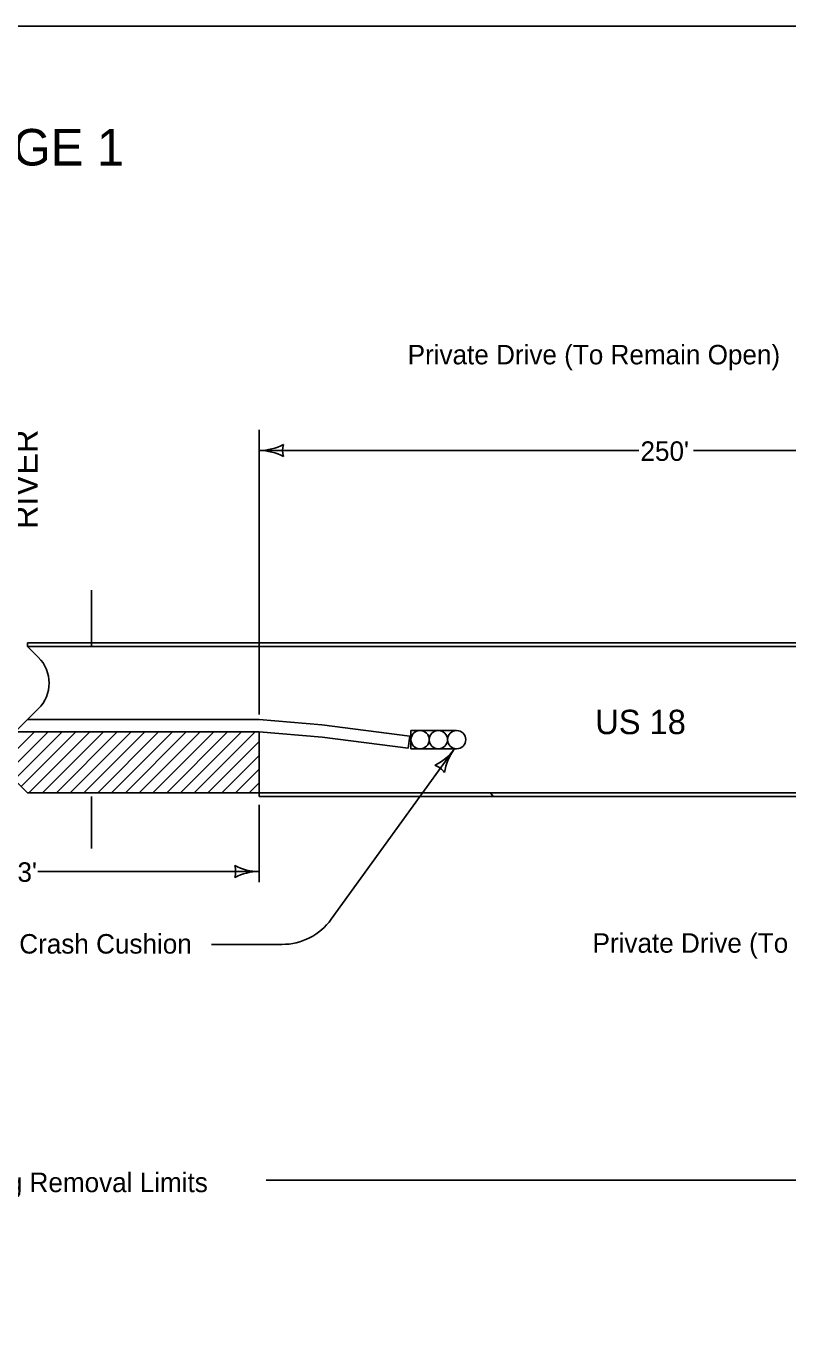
# Model space of a CAD drawing. Extents: x -2134934 to -2122394, y -2140205 to -2137036.
# Drawn here: x -2128661 to -2128036, y -2138106 to -2137036 of the extents above; entities that cross this region are included whole.
import ezdxf

# ---------------------------------------------------------------- set-up
doc = ezdxf.new("R2010")
doc.units = 0
for name, color, linetype in [('Barrier', 7, 'Continuous'), ('BridgeSuperStructureExisting', 7, 'Continuous'), ('Default', 7, 'Continuous'), ('dsnCellsNorthArrow', 7, 'Continuous'), ('DsnShtPlotIdentification', 7, 'Continuous'), ('DsnShtPlotShape', 7, 'Continuous')]:
    doc.layers.add(name, color=color, linetype=linetype)

msp = doc.modelspace()

# ---------------------------------------------------------------- linework, layer by layer
at = {"layer": 'BridgeSuperStructureExisting'}
for p, q in [((-2128470.1, -2137367.2), (-2128470.1, -2137601.1)), ((-2128158.6, -2137384.3), (-2128470.1, -2137384.3)), ((-2127812, -2137384.3), (-2128113.7, -2137384.3)), ((-2128607.6, -2137498.8), (-2128607.6, -2137545.2)), ((-2128660.1, -2137545.2), (-2128651.3, -2137553.9)), ((-2127160.1, -2137545.2), (-2128660.1, -2137545.2)), ((-2128660.1, -2137545.2), (-2128651.3, -2137553.9)), ((-2128651.3, -2137596.4), (-2128668.9, -2137613.9)), ((-2128651.3, -2137596.4), (-2128660.1, -2137605.2)), ((-2128660.1, -2137605.2), (-2128668.9, -2137613.9)), ((-2128470.1, -2137605.2), (-2128660.1, -2137605.2)), ((-2128470.1, -2137605.2), (-2128660.1, -2137605.2)), ((-2128660.1, -2137605.2), (-2128470.1, -2137605.2)), ((-2128660.1, -2137605.2), (-2128470.1, -2137605.2)), ((-2128418.6, -2137609.5), (-2128470.1, -2137605.2)), ((-2128470.1, -2137605.2), (-2128418.6, -2137609.5)), ((-2128470.1, -2137605.2), (-2128418.6, -2137609.5)), ((-2128346.6, -2137618.8), (-2128418.6, -2137609.5)), ((-2128346.6, -2137618.8), (-2128418.6, -2137609.5)), ((-2128418.6, -2137609.5), (-2128346.6, -2137618.8)), ((-2128418.6, -2137609.5), (-2128346.6, -2137618.8)), ((-2128654.4, -2137615.2), (-2128677.5, -2137638.3)), ((-2128643.1, -2137615.2), (-2128675.1, -2137647.2)), ((-2128631.8, -2137615.2), (-2128670.8, -2137654.2)), ((-2128670.1, -2137615.2), (-2128470.5, -2137615.2)), ((-2128670.1, -2137615.2), (-2128470.1, -2137615.2)), ((-2128620.4, -2137615.2), (-2128665.3, -2137660)), ((-2128609.1, -2137615.2), (-2128659.1, -2137665.2)), ((-2128597.8, -2137615.2), (-2128647.8, -2137665.2)), ((-2128586.5, -2137615.2), (-2128636.5, -2137665.2)), ((-2128575.2, -2137615.2), (-2128625.2, -2137665.2)), ((-2128563.9, -2137615.2), (-2128613.9, -2137665.2)), ((-2128552.6, -2137615.2), (-2128602.6, -2137665.2)), ((-2128591.2, -2137665.2), (-2128541.2, -2137615.2)), ((-2128529.9, -2137615.2), (-2128579.9, -2137665.2)), ((-2128518.6, -2137615.2), (-2128568.6, -2137665.2)), ((-2128507.3, -2137615.2), (-2128557.3, -2137665.2)), ((-2128496, -2137615.2), (-2128546, -2137665.2)), ((-2128484.7, -2137615.2), (-2128534.7, -2137665.2)), ((-2128473.4, -2137615.2), (-2128523.4, -2137665.2)), ((-2128470.5, -2137615.2), (-2128470.4, -2137615.2)), ((-2128470.4, -2137615.2), (-2128470.1, -2137615.2)), ((-2128470.1, -2137615.2), (-2128470.1, -2137665.2)), ((-2128470.1, -2137615.2), (-2128470.1, -2137615.2)), ((-2128470.1, -2137615.2), (-2128418.4, -2137619.5)), ((-2128470.1, -2137615.2), (-2128418.4, -2137619.5)), ((-2128418.4, -2137619.5), (-2128470.1, -2137615.2)), ((-2128470.1, -2137615.2), (-2128470.1, -2137665.2)), ((-2128418.4, -2137619.5), (-2128347.9, -2137628.7)), ((-2128418.4, -2137619.5), (-2128347.9, -2137628.7)), ((-2128347.9, -2137628.7), (-2128418.4, -2137619.5)), ((-2128347.9, -2137628.7), (-2128346.6, -2137618.8)), ((-2128346.6, -2137618.8), (-2128347.9, -2137628.7)), ((-2128346.6, -2137618.8), (-2128347.9, -2137628.7)), ((-2128345.6, -2137629.1), (-2128345.6, -2137614.1)), ((-2128345.6, -2137614.1), (-2128308.1, -2137614.1)), ((-2128345.6, -2137629.1), (-2128345.6, -2137614.1)), ((-2128345.6, -2137614.1), (-2128308.1, -2137614.1)), ((-2128470.1, -2137623.2), (-2128512.1, -2137665.2)), ((-2128310.2, -2137629.5), (-2128411, -2137769)), ((-2128308.1, -2137629.1), (-2128345.6, -2137629.1)), ((-2128308.1, -2137629.1), (-2128345.6, -2137629.1)), ((-2128470.1, -2137634.5), (-2128500.8, -2137665.2)), ((-2128470.1, -2137645.8), (-2128489.5, -2137665.2)), ((-2128668.9, -2137656.4), (-2128660.1, -2137665.2)), ((-2128470.1, -2137657.1), (-2128478.2, -2137665.2)), ((-2128607.6, -2137668.2), (-2128607.6, -2137710.9)), ((-2128470.1, -2137665.2), (-2127160.1, -2137665.2)), ((-2128470.1, -2137675.2), (-2128470.1, -2137738.5)), ((-2128470.1, -2137729.8), (-2128651.7, -2137729.8)), ((-2128451.5, -2137789.7), (-2128509.3, -2137789.7)), ((-2127805.1, -2137983.3), (-2128464.5, -2137983.3))]:
    msp.add_line(p, q, dxfattribs=at)
for points in [[(-2128660.1, -2137605.2), (-2128660.1, -2137605.2)], [(-2128660.1, -2137605.2), (-2128660.1, -2137605.2)], [(-2128470.5, -2137615.2), (-2128470.5, -2137615.2)], [(-2128308.1, -2137614.1), (-2128308.1, -2137614.1)], [(-2128308.1, -2137629.1), (-2128308.1, -2137629.1)], [(-2128470.1, -2137665.2), (-2128660.1, -2137665.2)]]:
    msp.add_lwpolyline(points, dxfattribs=at)
for centre in [(-2128338.1, -2137621.6), (-2128338.1, -2137621.6), (-2128323.1, -2137621.6), (-2128323.1, -2137621.6), (-2128308.1, -2137621.6), (-2128308.1, -2137621.6)]:
    msp.add_circle(centre, 7.5, dxfattribs=at)
for centre, radius, start, end in [((-2128672.5, -2137575.2), 30, 315, 45), ((-2128672.5, -2137575.2), 30, 315, 45), ((-2128308.1, -2137621.6), 7.5, 270.0028, 89.9972), ((-2128505.8, -2137729.8), 16.4, 342.2666, 17.7334), ((-2128470.1, -2137687.4), 42.5, 241.9275, 270), ((-2128470.1, -2137772.3), 42.5, 90, 118.0725), ((-2128451.5, -2137739.7), 50, 270, 324.138)]:
    msp.add_arc(centre, radius, start, end, dxfattribs=at)
at = {"layer": 'Default'}
msp.add_lwpolyline([(-2130232, -2137035.9), (-2127097, -2137035.9), (-2127097, -2139045.9), (-2130232, -2139045.9)], close=True, dxfattribs=at)
at = {"layer": 'DsnShtPlotIdentification'}
for p, q in [((-2127160.1, -2137542.2), (-2128660.1, -2137542.2)), ((-2127160.1, -2137542.2), (-2128660.1, -2137542.2)), ((-2128660.1, -2137542.2), (-2128660.1, -2137545.2)), ((-2127160.1, -2137545.2), (-2128660.1, -2137545.2)), ((-2128660.1, -2137545.2), (-2127810.1, -2137545.2)), ((-2128660.1, -2137665.2), (-2127159.5, -2137665.2)), ((-2128470.1, -2137665.2), (-2128470.1, -2137668.2)), ((-2128470.1, -2137668.2), (-2128470.1, -2137665.2)), ((-2128470.1, -2137668.2), (-2128278.1, -2137668.2)), ((-2128278.1, -2137668.2), (-2128280.3, -2137665.2)), ((-2128280.3, -2137665.2), (-2128278.1, -2137668.2)), ((-2127805.1, -2137665.2), (-2128280.3, -2137665.2)), ((-2128278.1, -2137668.2), (-2127805.1, -2137668.2))]:
    msp.add_line(p, q, dxfattribs=at)
for points in [[(-2128471.3, -2137545.2), (-2127158.8, -2137545.2)], [(-2127160.1, -2137665.2), (-2128470.1, -2137665.2)], [(-2128280.3, -2137665.2), (-2128469.7, -2137665.2), (-2128470.1, -2137665.2)], [(-2127160.1, -2137668.2), (-2128470.1, -2137668.2)]]:
    msp.add_lwpolyline(points, dxfattribs=at)
at = {"layer": 'DsnShtPlotShape'}
for centre, radius, start, end in [((-2128470.1, -2137341.8), 42.5, 270, 298.0725), ((-2128470.1, -2137426.8), 42.5, 61.9275, 90), ((-2128434.5, -2137384.3), 16.4, 162.2666, 197.7334), ((-2128344.4, -2137604.4), 42.5, 295.6285, 323.701), ((-2128275.9, -2137654.7), 42.5, 143.701, 171.7735), ((-2128331.3, -2137658.2), 16.4, 35.9676, 71.4343)]:
    msp.add_arc(centre, radius, start, end, dxfattribs=at)

# ---------------------------------------------------------------- texts
at = {"layer": 'Barrier'}
msp.add_text('STAGE 1', height=30, dxfattribs=at).set_placement((-2128750.3, -2137150.4))
at = {"layer": 'BridgeSuperStructureExisting'}
for s, p in [('Private Drive (To Remain Open)', (-2128348.3, -2137313.6)), ("250'", (-2128157.3, -2137392.8)), ("423'", (-2128692.2, -2137738.3)), ('Temporary Crash Cushion', (-2128776.3, -2137797.2)), ('Private Drive (To Remain Open)', (-2128196.6, -2137796.5)), ('Pavement Marking Removal Limits', (-2128842.8, -2137993))]:
    msp.add_text(s, height=16, dxfattribs=at).set_placement(p)
at = {"layer": 'dsnCellsNorthArrow'}
msp.add_text('RIVER', height=20, rotation=90, dxfattribs=at).set_placement((-2128651.8, -2137448.8))
msp.add_text('US 18', height=20, dxfattribs=at).set_placement((-2128194.4, -2137617.1))

doc.saveas('drawing.dxf')
